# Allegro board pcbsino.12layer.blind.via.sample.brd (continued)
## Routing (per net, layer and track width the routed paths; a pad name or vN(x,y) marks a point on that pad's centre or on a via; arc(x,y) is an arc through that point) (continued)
SODIMM_ETH1_LED2_LINK_ACT_1000/: length 16.2
  TOP w0.114: U19.37 47.29,9.42 R303.2 v2(47.34,9.36)
  INT_L3 w0.091: v2(47.34,9.36) 47.34,6.79 47.99,6.14 50.64,6.14 50.95,5.83 51.97,5.83 52.29,6.16 v3(52.29,6.31)
  SIG_L10 w0.091: v5(52.77,6.34) 52.32,6.34 v3(52.29,6.31)
  BOTTOM w0.114: v5(52.77,6.34) 52.82,6.38 XP1.16
SODIMM_ETH1_MDI0_N: length 15.8
  TOP w0.102: v2(53.41,4.05) 53.33,4.13 53.33,4.59 53.66,4.92 53.66,12.21 53.41,12.46 53,12.46 52.9,12.56 U19.3
  INT_L3 w0.089: v3(56.98,3.36) 56.75,3.58 55.5,3.58 54.74,4.34 53.41,4.34 53.32,4.25 53.32,4.14 v2(53.41,4.05)
  SIG_L10 w0.089: v5(57.69,3.46) 57.67,3.43 57.47,3.43 57.36,3.54 57.17,3.54 v3(56.98,3.36)
  BOTTOM w0.102: XP1.6 57.77,3.38 v5(57.69,3.46)
SODIMM_ETH1_MDI0_P: length 15.7
  TOP w0.102: U19.2 52.99,12.16 53.04,12.21 53.31,12.21 53.41,12.1 53.41,5.03 53.08,4.7 53.08,4.11 v2(53.02,4.05)
  INT_L3 w0.089: v2(53.02,4.05) 53.08,4.11 53.08,4.35 53.31,4.59 54.84,4.59 55.6,3.82 56.84,3.82 v3(56.98,3.96)
  SIG_L10 w0.089: v5(57.7,3.98) 57.5,3.78 57.16,3.78 v3(56.98,3.96)
  BOTTOM w0.102: XP1.8 v5(57.7,3.98)
SODIMM_ETH1_MDI1_N: length 14.1
  TOP w0.102: U19.6 52.99,13.76 53.06,13.68 53.99,13.68 54.6,13.07 54.6,5.16 54.65,5.12 v2(54.65,5.08)
  INT_L3 w0.089: v3(57.2,5.2) 57.02,5.39 54.64,5.39 54.55,5.3 54.55,5.17 v2(54.65,5.08)
  SIG_L10 w0.089: v3(57.2,5.2) 57.38,5.39 57.56,5.39 57.65,5.3 57.65,5.29 v5(57.68,5.26)
SODIMM_ETH1_MDI1_P: length 14.2
  TOP w0.102: v2(54.25,5.07) 54.25,5.07 54.25,5.08 54.35,5.17 54.35,12.97 53.88,13.43 53.06,13.43 52.99,13.36 U19.5
  INT_L3 w0.089: v3(57.2,5.81) 57.02,5.63 54.54,5.63 54.31,5.4 54.31,5.13 v2(54.25,5.07)
  SIG_L10 w0.089: v5(57.68,5.84) 57.6,5.76 57.6,5.72 57.51,5.63 57.38,5.63 v3(57.2,5.81)
SODIMM_ETH1_MDI2_N: length 13.3
  TOP w0.102: U19.8 52.99,14.56 53.06,14.48 54.73,14.48 55.44,13.77 v2(55.44,7.13)
  INT_L3 w0.089: v3(58.13,7) 57.94,7.19 55.5,7.19 v2(55.44,7.13)
  SIG_L10 w0.089: v3(58.13,7) v5(57.64,7)
SODIMM_ETH1_MDI2_P: length 13.1
  TOP w0.102: U19.7 52.99,14.16 53.06,14.23 54.62,14.23 55.19,13.67 55.19,7.48 v2(55.03,7.33)
  INT_L3 w0.089: v3(58.12,7.64) 57.91,7.43 55.14,7.43 v2(55.03,7.33)
  SIG_L10 w0.089: v3(58.12,7.64) 58.06,7.57 v5(57.63,7.57)
SODIMM_ETH1_MDI3_N: length 12.9
  TOP w0.102: v2(56.18,9.03) 56.28,9.13 56.28,14.47 55.06,15.68 53.06,15.68 52.99,15.76 U19.11
  INT_L3 w0.089: v2(56.18,9.03) 56.32,9.17 57.05,9.17 57.28,8.94 58.41,8.94 v3(58.56,8.79)
  SIG_L10 w0.089: v5(58.08,8.8) 58.2,8.8 58.55,8.8 v3(58.56,8.79)
SODIMM_ETH1_MDI3_P: length 12.8
  TOP w0.102: U19.10 52.99,15.36 53.06,15.43 54.96,15.43 56.02,14.36 56.02,9.41 v2(55.82,9.21)
  INT_L3 w0.089: v3(58.56,9.41) 58.56,9.31 58.44,9.18 57.38,9.18 57.15,9.41 56.02,9.41 v2(55.82,9.21)
  SIG_L10 w0.089: v5(58.09,9.41) 58.21,9.41 58.21,9.41 58.56,9.41 v3(58.56,9.41)
SODIMM_GPIO1_16: length 66.6
  TOP w0.114: XP1.151 58.62,49.57 v2(57.55,49.57)
  TOP w0.12: v8(19.87,19.97) U6.D27
  INT_L3 w0.091: v3(44.47,50.86) 45.15,51.54 45.83,51.54 46.09,51.8 56.23,51.8 57.37,50.66 57.37,49.75 v2(57.55,49.57)
  SIG_L5 w0.091: v3(44.47,50.86) 44.47,50.43 41.98,47.94 41.98,44.84 40.86,43.73 31.87,43.73 30.23,42.09 30.23,41.97 30.2,41.94 30.2,30.09 30.23,30.06 30.23,24.97 29.66,24.4 29.36,24.4 28.49,23.53 28.49,23.26 26.5,21.27 25.62,21.27 24.7,20.35 22.8,20.35 22.04,19.6 20.25,19.6 v8(19.87,19.97)
SODIMM_GPIO1_17: length 86
  TOP w0.114: XP1.149 58.58,48.93 56.58,48.93 v7(56.48,48.83)
  TOP w0.12: U6.C28 19.01,19.11 19.01,17.24 19.37,16.88 v2(19.55,16.88)
  INT_L3 w0.091: v2(19.55,16.88) 20.13,16.29 20.13,15.99 v3(20.16,15.96)
  SIG_L5 w0.091: v7(56.48,48.83) 56.48,47.84 55.96,47.31 55.96,38.49 53.82,36.35 53.82,33.6 53.29,33.07 53.29,31.76 51.47,29.95 51.47,23.06 53.66,20.87 53.66,17.7 51.61,15.65 51.61,14.79 46.8,9.98 45.62,9.98 44.21,8.57 44.19,8.55 41.72,6.09 32.74,6.09 32.5,5.85 26.53,5.85 20.16,12.22 v3(20.16,15.96)
SODIMM_GPIO2_2: length 29.2
  TOP w0.114: v2(56.53,36.56) 54.78,38.32 52.95,38.32 52.92,38.34 v2(52.91,38.34)
  TOP w0.12: v8(39.06,27.98) U6.P4
  INT_L3 w0.091: v8(39.06,27.98) 39.06,28.01 39.69,28.64 41.22,28.64 42.26,29.68 42.26,31.92 42.64,32.3 44.22,32.3 44.58,32.66 44.89,32.66 45.39,33.15 45.9,33.15 47.82,35.07 50.71,35.07 52.65,37 52.65,38.08 v2(52.91,38.34) ; v2(57.62,32.78) 57.62,33.34 56.79,34.18 56.79,36.31 v2(56.53,36.56)
SODIMM_GPIO3_29/AVID: length 56.7
  TOP w0.12: v8(40.67,22.37) U6.G2
  INT_L3 w0.091: v3(47.79,48.68) 48.24,49.13 54.92,49.13 56.15,47.89 56.15,36.44 56.43,36.16 56.43,32.65 56.86,32.22 v2(57.7,32.22)
  SIG_L10 w0.091: v3(47.79,48.68) 47.73,48.62 47.73,45.34 47.41,45.02 47.41,43.79 44.22,40.59 44.22,40.35 44.22,35.02 44.36,34.88 44.36,34.7 44.36,24.45 44.06,24.16 43.2,23.3 42.27,23.3 41.97,23.3 41.59,23.3 v8(40.67,22.37)
SODIMM_GPIO4_0/DEC_INTREQ: length 24.1
  TOP w0.114: v7(56.18,25.91) 56.45,26.18 XP1.73
  TOP w0.12: v8(37.47,22.37) U6.G6
  BOTTOM w0.114: v8(37.47,22.37) 37.86,21.98 38.1,21.98 38.1,21.98 38.43,21.98 38.43,21.98 39.71,21.98 39.71,21.98 40.04,21.98 40.04,21.98 40.83,21.98 40.83,21.98 40.98,21.98 41.57,22.57 42.64,22.57 43.25,21.96 44.93,21.96 44.93,21.95 45.17,21.95 45.18,21.96 48.05,21.96 49.34,23.25 51.76,23.25 52.98,24.47 54.58,24.47 56.01,25.91 v7(56.18,25.91)
SODIMM_GPIO5_4: length 49.6
  TOP w0.12: v8(31.87,22.37) U6.G13
  SIG_L10 w0.091: v8(31.87,22.37) 31.93,22.37 32.35,22.8 32.88,22.8 33.06,22.97 33.06,23.37 34.07,24.37 34.07,24.37 34.09,24.39 34.33,24.39 34.59,24.65 34.59,24.88 37.28,27.57 40.45,27.57 42.34,29.46 42.34,33.8 42.15,33.99 42.15,41.56 46.32,45.73 46.32,48.73 46.73,49.14 53.53,49.14 55.21,50.81 v5(55.21,51.3)
  BOTTOM w0.114: v5(55.21,51.3) 56.5,52.58 XP1.162
SODIMM_GPIO6_16/CLKOUT1: length 61.3
  INT_L3 w0.091: v2(57.57,34.02) 57.27,34.32 v3(57.27,34.51)
  SIG_L5 w0.091: v3(57.27,34.51) 57.27,34.11 52.55,29.39 52.55,23.61 54.54,21.63 54.54,15.4 47.76,8.62 45.92,8.62 45.78,8.48 44.97,8.48 41.97,5.47 38.25,5.47 37.78,5 37.44,5 36.97,5.47 v3(36.29,5.47)
  SIG_L10 w0.091: v3(36.29,5.47) 35.89,5.88 32.42,5.88 32.27,6.03 32.17,6.03 25.72,12.48 25.72,14.87 v5(25.59,15)
SODIMM_GPIO6_18: length 60.3
  TOP w0.12: v8(27.87,20.77) U6.E17
  SIG_L5 w0.091: v8(27.87,20.77) 28.29,21.2 28.29,21.81 28.48,22 28.82,22 29.04,22.22 29.04,22.23 29.09,22.28 29.09,22.53 29.31,22.75 29.97,22.75 30.81,23.6 31.37,23.6 31.56,23.79 31.56,24.3 31.46,24.4 31.46,27.54 31.27,27.73 31.27,28.45 31.47,28.65 31.47,29.13 31.27,29.33 31.27,29.64 30.69,30.22 30.69,30.97 31.44,31.72 31.44,33.08 30.69,33.83 30.69,36.2 31.52,37.03 31.52,39.11 31.67,39.26 31.67,40.59 31.61,40.64 31.61,41.87 32.53,42.79 41.27,42.79 42.63,44.15 42.63,46.42 43.04,46.83 43.04,48.2 44.57,49.72 44.82,49.72 46.17,51.07 v3(46.27,51.07)
  SIG_L10 w0.091: v3(46.27,51.07) 47.26,50.08 50.21,50.08 50.39,50.26 53.61,50.26 55.06,51.7 56.23,51.7 57.75,50.18 v5(57.85,50.18)
  BOTTOM w0.114: v5(57.85,50.18) XP1.154
SODIMM_GPIO6_19: length 91
  TOP w0.114: XP1.193 58.62,62.18 56.21,62.18 v7(56.05,62.34) ; v2(22.15,13.56) 21.02,14.69 R173.2
  INT_L3 w0.091: v2(22.15,13.56) 22.15,13.31 22.66,12.8 22.84,12.8 v3(22.93,12.71)
  SIG_L5 w0.091: v3(22.93,12.71) 23.56,12.09 23.56,10.7 26.95,7.31 27.9,7.31 28.16,7.05 40.6,7.05 44.4,10.85 46.44,10.85 50.35,14.76 50.35,16.26 51.87,17.78 51.87,21.62 50.82,22.67 50.82,30.22 52.64,32.04 52.64,33.34 53.16,33.87 53.16,36.62 55.08,38.54 55.08,51.22 55.87,52 55.87,53.33 55.55,53.65 55.55,61.84 v7(56.05,62.34)
SODIMM_HDMI1_CEC: length 62.9
  TOP w0.114: v2(25.37,18.4) 25.52,18.41 U6.B20
  INT_L3 w0.091: v2(25.37,18.4) 25.37,18.35 25.21,18.2 25.21,16.37 24.35,15.51 24.35,14.54 23.78,13.97 23.78,13.93 23.76,13.91 23.76,12.53 21.66,10.43 v3(21.66,9.59)
  SIG_L10 w0.091: v5(58.95,11.77) 59.29,11.43 59.29,2.09 57.85,0.65 46.3,0.65 43.37,3.57 37.31,3.57 37.1,3.36 33.41,3.36 30.99,5.78 26.69,5.78 22.88,9.59 v3(21.66,9.59)
SODIMM_HDMI1_CLOCK_N: length 64.4
  TOP w0.102: U6.AG16 29.07,38.94 28.65,39.37 28.65,40.04 v2(28.31,40.37)
  INT_L3 w0.089: v2(28.31,40.37) 28.46,40.54 28.97,40.54 30.81,42.38 41.67,42.38 44.49,39.56 47.07,39.56 47.63,39 49.48,39 49.75,39.27 50.17,39.27 50.31,39.13 v3(50.31,39.1)
  SIG_L10 w0.089: v3(50.31,39.1) 50.54,39.33 51.03,39.33 53.04,37.33 53.04,37.09 53.26,36.87 53.42,36.87 53.5,36.79 53.5,36.68 53.42,36.6 53.26,36.6 53.04,36.38 53.04,36.07 53.26,35.85 53.42,35.85 53.5,35.77 53.5,35.66 53.42,35.59 53.26,35.59 53.04,35.37 53.04,35.06 53.26,34.84 53.42,34.84 53.5,34.76 53.5,34.65 53.42,34.57 53.26,34.57 53.04,34.35 53.04,28.7 52.89,28.55 52.89,25.82 53.04,25.67 53.04,23.38 54.33,22.09 54.33,14.45 55.34,13.45 55.65,13.45 55.8,13.6 55.91,13.6 55.99,13.52 55.99,13.41 55.84,13.26 55.84,12.95 56.06,12.73 56.37,12.73 56.52,12.88 56.63,12.88 56.71,12.81 56.71,12.7 56.55,12.54 56.55,12.23 57.09,11.7 57.09,11.16 56.92,10.99 56.52,10.99 56.43,11.07 v5(56.43,11.21)
  BOTTOM w0.102: XP1.32 57.36,11.18 57.14,10.96 56.56,10.96 56.43,11.09 v5(56.43,11.21)
SODIMM_HDMI1_CLOCK_P: length 64.5
  TOP w0.102: v2(28.24,40.81) 28.36,40.81 28.72,40.45 28.72,40.33 28.9,40.15 28.9,39.74 U6.AH16
  INT_L3 w0.089: v3(50.31,39.71) 50.11,39.51 49.65,39.51 49.38,39.24 47.73,39.24 47.17,39.8 44.59,39.8 41.77,42.62 30.71,42.62 28.87,40.78 28.26,40.78 v2(28.24,40.81)
  SIG_L10 w0.089: v5(56.46,10.58) 56.48,10.58 56.65,10.74 57.02,10.74 57.33,11.06 57.33,11.8 56.8,12.33 56.8,12.44 56.95,12.6 56.95,12.91 56.73,13.13 56.42,13.13 56.27,12.97 56.16,12.97 56.08,13.05 56.08,13.16 56.23,13.31 56.23,13.62 56.01,13.84 55.7,13.84 55.55,13.69 55.44,13.69 54.58,14.55 54.58,22.19 53.28,23.48 53.28,25.77 53.13,25.92 53.13,28.45 53.28,28.6 53.28,34.25 53.36,34.33 53.52,34.33 53.74,34.55 53.74,34.86 53.52,35.08 53.36,35.08 53.28,35.16 53.28,35.27 53.36,35.34 53.52,35.34 53.74,35.56 53.74,35.87 53.52,36.09 53.36,36.09 53.28,36.17 53.28,36.28 53.36,36.36 53.52,36.36 53.74,36.58 53.74,36.89 53.52,37.11 53.36,37.11 53.28,37.19 53.28,37.43 51.13,39.57 50.45,39.57 v3(50.31,39.71)
  BOTTOM w0.102: XP1.30 v5(56.46,10.58)
SODIMM_HDMI1_DATA0_N: length 64.1
  TOP w0.102: v2(27.37,42.91) 27.42,42.86 27.42,40.4 27.85,39.97 27.85,39.37 28.27,38.94 U6.AG17
  INT_L3 w0.089: v3(49.11,39.92) 48.92,40.1 48.92,40.33 48.61,40.64 44.8,40.64 42.1,43.33 27.79,43.33 27.48,43.02 v2(27.37,42.91)
  SIG_L10 w0.089: v5(55.02,12.9) 54.89,12.78 53.74,12.78 53.48,13.03 53.48,13.49 53.71,13.72 53.71,14.09 53.48,14.32 53.48,14.5 53.71,14.73 53.71,15.11 53.48,15.34 53.48,15.52 53.71,15.75 53.71,16.13 53.48,16.35 53.48,16.53 53.71,16.76 53.71,17.14 53.48,17.37 53.48,17.81 53.87,18.19 53.87,21.68 52.54,23 52.54,37.01 51.01,38.54 49.66,38.54 48.92,39.28 48.92,39.73 v3(49.11,39.92)
  BOTTOM w0.102: XP1.38 57.26,12.98 57.07,12.79 55.14,12.79 v5(55.02,12.9)
SODIMM_HDMI1_DATA0_P: length 64.1
  TOP w0.102: v2(27.8,42.91) 27.78,42.91 27.68,42.81 27.68,42.42 27.8,42.29 27.8,42.12 27.68,41.99 27.68,41.81 27.8,41.68 27.8,41.51 27.68,41.38 27.68,41.2 27.8,41.07 27.8,40.9 27.68,40.77 27.68,40.5 28.1,40.08 28.1,39.74 U6.AH17
  INT_L3 w0.089: v3(48.5,39.92) 48.68,40.1 48.68,40.23 48.51,40.4 44.7,40.4 42,43.09 34.44,43.09 34.34,42.99 34.17,42.99 34.07,43.09 33.91,43.09 33.8,42.99 33.64,42.99 33.54,43.09 33.37,43.09 33.27,42.99 33.11,42.99 33,43.09 32.84,43.09 32.74,42.99 32.57,42.99 32.47,43.09 32.31,43.09 32.2,42.99 32.04,42.99 31.94,43.09 31.77,43.09 31.67,42.99 31.51,42.99 31.4,43.09 31.24,43.09 31.14,42.99 30.97,42.99 30.87,43.09 30.71,43.09 30.6,42.99 30.44,42.99 30.34,43.09 30.17,43.09 30.07,42.99 29.91,42.99 29.8,43.09 29.64,43.09 29.54,42.99 29.37,42.99 29.27,43.09 29.1,43.09 29,42.99 28.84,42.99 28.74,43.09 28.57,43.09 28.47,42.99 28.3,42.99 28.2,43.09 27.89,43.09 27.8,43 v2(27.8,42.91)
  SIG_L10 w0.089: v3(48.5,39.92) 48.68,39.73 48.68,39.18 49.56,38.3 50.91,38.3 52.3,36.91 52.3,22.9 53.62,21.58 53.62,18.29 53.24,17.91 53.24,17.27 53.47,17.04 53.47,16.86 53.24,16.63 53.24,16.26 53.47,16.03 53.47,15.85 53.24,15.62 53.24,15.24 53.47,15.01 53.47,14.83 53.24,14.6 53.24,14.22 53.47,13.99 53.47,13.81 53.24,13.59 53.24,12.93 53.64,12.54 54.91,12.54 v5(55.03,12.41)
  BOTTOM w0.102: XP1.36 57.25,12.38 57.09,12.54 55.16,12.54 v5(55.03,12.41)
SODIMM_HDMI1_DATA1_N: length 64.9
  TOP w0.102: U6.AG18 27.09,39.15 27.09,39.81 26.74,40.17 26.74,43.27 v2(26.64,43.37)
  INT_L3 w0.089: v2(26.64,43.37) 26.67,43.41 26.67,43.86 26.9,44.09 42.3,44.09 45.09,41.3 48.92,41.3 49.31,40.92 50.02,40.92 v3(50.16,41.06)
  SIG_L10 w0.089: v5(57.17,14.77) 57,14.6 55.69,14.6 55.29,15 55.29,22.67 54.63,23.33 54.63,26.8 56.01,28.18 56.01,30.49 55.62,30.87 55.62,33.13 56.15,33.67 56.15,37.02 52.87,40.3 51.62,40.3 50.99,40.92 50.32,40.92 50.18,41.06 v3(50.16,41.06)
  BOTTOM w0.102: XP1.44 57.18,14.78 v5(57.17,14.77)
SODIMM_HDMI1_DATA1_P: length 65
  TOP w0.102: U6.AH18 27.47,39.8 26.99,40.27 26.99,40.93 27.09,41.03 27.09,41.23 26.99,41.33 26.99,41.54 27.09,41.64 27.09,41.84 26.99,41.94 26.99,42.15 27.09,42.25 27.09,42.45 26.99,42.55 26.99,43.4 v2(27.02,43.42)
  INT_L3 w0.089: v2(27.02,43.42) 26.92,43.52 26.92,43.76 27,43.85 27.45,43.85 27.58,43.73 27.72,43.73 27.85,43.85 27.99,43.85 28.11,43.73 28.25,43.73 28.38,43.85 28.52,43.85 28.65,43.73 28.79,43.73 28.91,43.85 29.05,43.85 29.18,43.73 29.32,43.73 29.45,43.85 29.59,43.85 29.71,43.73 29.85,43.73 29.98,43.85 30.12,43.85 30.25,43.73 30.39,43.73 30.51,43.85 30.65,43.85 30.78,43.73 30.92,43.73 31.05,43.85 31.19,43.85 31.31,43.73 31.45,43.73 31.58,43.85 31.72,43.85 31.85,43.73 31.99,43.73 32.11,43.85 32.25,43.85 32.38,43.73 32.52,43.73 32.65,43.85 42.2,43.85 44.99,41.06 48.82,41.06 49.21,40.68 49.93,40.68 v3(50.16,40.45)
  SIG_L10 w0.089: v3(50.16,40.45) 50.39,40.68 50.89,40.68 51.52,40.06 52.77,40.06 55.91,36.92 55.91,33.77 55.38,33.23 55.38,30.77 55.76,30.39 55.76,28.28 54.39,26.9 54.39,23.23 55.05,22.57 55.05,14.9 55.59,14.36 57,14.36 v5(57.17,14.19)
  BOTTOM w0.102: XP1.42 57.17,14.18 v5(57.17,14.19)
SODIMM_HDMI1_DATA2_N: length 65.4
  TOP w0.102: v2(25.68,43.93) 25.72,43.89 25.72,40.35 26.25,39.82 26.25,39.37 26.67,38.94 U6.AG19
  INT_L3 w0.089: v3(51.81,41.75) 51.67,41.61 51.16,41.61 50.82,41.95 45.51,41.95 42.63,44.83 26.09,44.83 25.76,44.5 25.76,44.01 v2(25.68,43.93)
  SIG_L10 w0.089: v3(51.81,41.75) 51.91,41.64 52.61,41.64 56.72,37.53 56.72,33.42 56.29,32.98 56.29,31.35 56.72,30.92 56.72,27.85 55.36,26.49 55.36,23.67 55.95,23.09 55.95,16.48 56.04,16.39 56.96,16.39 v5(57.14,16.57)
  BOTTOM w0.102: v5(57.14,16.57) 57.15,16.58 XP1.50
SODIMM_HDMI1_DATA2_P: length 65.3
  TOP w0.102: v2(26.06,43.96) 25.98,43.87 25.98,43.19 26.13,43.04 26.13,42.89 25.98,42.74 25.98,42.58 26.13,42.43 26.13,42.28 25.98,42.13 25.98,41.97 26.13,41.82 26.13,41.67 25.98,41.52 25.98,41.36 26.13,41.21 26.13,41.06 25.98,40.91 25.98,40.45 26.51,39.92 26.51,39.73 U6.AH19
  INT_L3 w0.089: v2(26.06,43.96) 26,44.02 26,44.4 26.19,44.59 26.38,44.59 26.48,44.49 26.64,44.49 26.74,44.59 26.91,44.59 27.01,44.49 27.18,44.49 27.28,44.59 27.44,44.59 27.54,44.49 27.71,44.49 27.81,44.59 27.98,44.59 28.08,44.49 28.24,44.49 28.34,44.59 28.51,44.59 28.61,44.49 28.78,44.49 28.88,44.59 29.04,44.59 29.14,44.49 29.31,44.49 29.41,44.59 29.58,44.59 29.68,44.49 29.84,44.49 29.94,44.59 42.53,44.59 45.41,41.71 50.72,41.71 51.06,41.36 51.58,41.36 v3(51.81,41.14)
  SIG_L10 w0.089: v3(51.81,41.14) 51.81,41.16 52.05,41.4 52.51,41.4 56.48,37.43 56.48,33.52 56.05,33.08 56.05,31.26 56.48,30.82 56.48,27.95 55.12,26.59 55.12,23.57 55.71,22.99 55.71,16.38 55.94,16.15 57.01,16.15 v5(57.17,15.99)
  BOTTOM w0.102: XP1.48 57.18,15.98 v5(57.17,15.99)
SODIMM_HDMI1_DDC_SCL: length 53.7
  TOP w0.114: v2(52.22,3.31) 52.22,3.31 52.3,3.23 52.46,3.23 52.6,3.37 53.99,3.37 56.61,5.98 56.61,9.08 56.91,9.38 XP1.25
  TOP w0.12: v8(21.47,19.17) U6.C25
  INT_L3 w0.091: v2(52.22,3.31) 52.21,3.31 52.21,3.37 v3(51.96,3.62)
  SIG_L10 w0.091: v8(21.47,19.17) 21.84,18.81 21.84,15.28 21.63,15.07 21.63,13.66 22.42,12.87 22.42,12.61 23.46,11.57 25.98,11.57 32.02,5.53 32.15,5.53 33.06,4.61 33.97,4.61 34.13,4.77 36.09,4.77 36.16,4.7 42.72,4.7 43.55,3.87 46.14,3.87 47.61,5.35 50.54,5.35 51.96,3.93 v3(51.96,3.62)
SODIMM_HDMI1_DDC_SDA: length 59.1
  TOP w0.114: XP1.31 58.8,11.18 v2(58.84,11.14)
  TOP w0.12: U6.F17 27.87,21.58 v8(27.86,21.58)
  INT_L3 w0.091: v2(58.84,11.14) 58.79,11.09 58.79,10.68 v3(58.78,10.66)
  SIG_L10 w0.091: v3(58.78,10.66) 59.07,10.36 59.07,2.18 57.8,0.91 56.07,0.91 55.47,1.51 55.47,2.5 54.25,3.72 53.03,3.72 51.05,5.7 47.52,5.7 46.65,4.84 45.05,4.84 43.81,6.08 43.35,6.08 43.26,6.18 36.45,6.18 36.16,6.46 32.35,6.46 26.93,11.88 26.93,14.82 27.12,15.01 27.12,18.48 26.67,18.93 26.67,20.79 27.29,21.42 27.7,21.42 v8(27.86,21.58)
SODIMM_HDMI1_HPD: length 65.8
  TOP w0.114: U6.B21 v2(24.66,18.4)
  INT_L3 w0.091: v3(21.54,8.94) 21.25,9.23 21.25,10.4 23.51,12.66 23.51,14.01 24.02,14.52 24.02,15.56 24.86,16.4 24.86,17.95 24.66,18.15 v2(24.66,18.4)
  SIG_L10 w0.091: v3(21.54,8.94) 23.22,8.94 26.64,5.52 30.84,5.52 33.23,3.14 37.19,3.14 37.4,3.35 43.11,3.35 46.03,0.43 57.69,0.43 57.71,0.43 57.94,0.43 58,0.49 58.02,0.49 58.06,0.55 59.51,2 59.51,2.18 59.51,13.17 v5(59.12,13.55)
SODIMM_I2C5_SCL/UART6_TXD: length 63.4
  INT_L3 w0.091: v2(57.85,42.99) 57.73,42.86 57.73,41.11 v3(57.6,40.98)
  SIG_L5 w0.091: v3(45.61,8.88) 47.71,8.88 54.32,15.49 54.32,21.54 52.34,23.52 52.34,29.48 56.38,33.53 56.38,35.8 57.6,37.02 v3(57.6,40.98)
  SIG_L10 w0.091: v3(45.61,8.88) 45.43,9.06 44.65,9.06 44.34,8.74 39.05,8.74 36.29,11.5 35.33,11.5 34.08,12.75 33.61,12.75 32.24,14.12 32.24,16.67 31.94,16.97 31.94,18.73 32.48,19.27 v5(32.55,19.27)
SODIMM_I2C5_SDA/UART6_RXD: length 64.8
  INT_L3 w0.091: v3(56.74,41.36) 57.34,41.97 57.34,43.98 58.11,44.74 v2(58.11,44.79)
  SIG_L5 w0.091: v3(46.07,9.36) 47.88,9.36 54.1,15.58 54.1,21.06 52.12,23.04 52.12,29.66 54.96,32.5 54.96,36.78 56.74,38.55 v3(56.74,41.36)
  SIG_L10 w0.091: v3(46.07,9.36) 44.64,9.36 44.25,8.96 39.14,8.96 36.63,11.47 36.38,11.72 35.42,11.72 34.17,12.97 34.03,12.97 32.46,14.54 32.46,16.76 32.22,17 32.22,17.92 v5(32.26,17.96)
  BOTTOM w0.114: v5(32.26,17.96) 32.54,18.23 R243.2
SODIMM_LDOUSB_IN: length 24.4
  TOP w0.114: R50.1 41.27,52.57 42.1,52.57 TP16.1 42.89,53.35 v2(42.89,54.01)
  INT_L3 w0.091: v2(42.89,54.01) 43.93,55.05 46.3,55.05 47.72,56.48 47.72,58.53 48.51,59.32 48.51,60.24 50.74,62.47 52.35,62.47 52.44,62.56 v3(52.44,62.57)
  SIG_L10 w0.091: v3(52.44,62.57) 52.47,62.57 52.67,62.78 v5(57.14,62.78)
  BOTTOM w0.114: XP1.196 v5(57.14,62.78)
SODIMM_MCASP2_ACLKX: length 62.1
  TOP w0.114: XP1.137 56.43,45.38 v2(55.67,46.14) ; v2(26.61,17.62) 26.67,17.67 U6.A19
  INT_L3 w0.091: v2(26.61,17.62) 26.59,17.59 26.59,17.13 v3(26.66,17.06) ; v2(55.67,46.14) 54.93,46.88 53.5,46.88 52.3,48.07 49.97,48.07 49.22,48.83 48.63,48.83 47.95,48.15 44.52,48.15 43.98,47.61 v3(43.83,47.61)
  SIG_L5 w0.091: v3(43.83,47.61) 43.76,47.54 43.76,47.23 42.85,46.33 42.85,43.91 41.37,42.43 32.71,42.43 31.83,41.56 31.83,40.73 31.96,40.6 31.96,37.24 32.29,36.9 32.29,31.83 32.01,31.55 31.71,31.55 31.49,31.33 31.49,30.53 31.49,30.53 31.49,29.42 32.02,28.89 32.02,28.66 31.49,28.13 31.49,27.82 32.07,27.24 32.07,25.15 32.29,24.93 32.29,23.64 31.28,22.63 31.28,21.99 27.13,17.83 26.69,17.39 26.69,17.08 v3(26.66,17.06)
SODIMM_MCASP2_AXR0: length 62.8
  TOP w0.114: v2(29.53,19.09) 29.85,18.77 U6.B15 ; XP1.139 57.25,45.98 57.22,46.01 56.25,46.01 v2(55.67,46.6)
  INT_L3 w0.091: v3(29.51,18.28) 29.53,18.3 v2(29.53,19.09) ; v2(55.67,46.6) 55.14,47.13 53.81,47.13 v3(52.98,47.97)
  SIG_L5 w0.091: v3(29.51,18.28) 29.28,18.05 29.28,16.81 32.35,13.74 43.17,13.74 47.34,17.92 47.34,19.77 48.13,20.55 48.13,32.11 51.19,35.17 51.19,46.18 v3(52.98,47.97)
SODIMM_MCASP2_AXR1: length 61.4
  TOP w0.114: v2(29.48,17.59) 29.49,17.59 U6.A15 ; v2(55.62,47.51) 56.15,47.51 56.48,47.18 XP1.143
  INT_L3 w0.091: v2(55.62,47.51) 54.17,47.51 53.2,48.48 v3(51.99,48.48) ; v3(29.68,17.1) 29.48,17.31 v2(29.48,17.59)
  SIG_L5 w0.091: v3(51.99,48.48) 50.97,47.46 50.97,35.26 47.91,32.2 47.91,20.64 47.12,19.86 47.12,18.01 43.08,13.96 32.44,13.96 29.68,16.72 v3(29.68,17.1)
SODIMM_MCASP2_FSX: length 62
  TOP w0.114: XP1.145 56.57,47.78 56.2,48.15 v2(55.19,48.15) ; 27.47,17.43 27.47,17.39 v2(27.47,17.39)
  TOP w0.12: U6.A18 27.47,17.43
  INT_L3 w0.091: v2(55.19,48.15) 55.01,48.32 v3(54.07,48.32) ; v2(27.47,17.39) 27.75,17.11 v3(27.93,17.11)
  SIG_L5 w0.091: v3(54.07,48.32) 54.07,45.78 51.41,43.12 51.41,35.07 49.79,33.45 49.79,31.02 49.04,30.26 49.04,24.65 48.45,24.06 48.45,20.57 47.56,19.68 47.56,17.83 43.26,13.53 31.51,13.53 v3(27.93,17.11)
SODIMM_MICROSD_MMC1_CLK: length 34.4
  TOP w0.12: v8(37.47,32.77) U6.W6
  SIG_L5 w0.091: v3(41.9,26.38) 41.67,26.15 41.09,26.15 41.01,26.23 41.01,26.42 40.93,26.51 40.81,26.51 40.73,26.42 40.73,26.23 40.65,26.15 40.43,26.15 40.1,26.48 40.1,28.61 40,28.72 38.12,28.72 37.47,29.36 v8(37.47,32.77)
  SIG_L10 w0.091: v3(41.9,26.38) 41.27,26.38 40.86,25.97 40.86,24.63 41.27,24.22 42.89,24.22 v5(42.97,24.14)
  BOTTOM w0.114: XP1.80 56.79,27.98 54.22,25.41 52.57,25.41 51.21,24.05 48.54,24.05 47.85,23.36 43.73,23.36 42.97,24.12 v5(42.97,24.14)
SODIMM_MICROSD_MMC1_CMD: length 34.4
  TOP w0.12: v8(37.47,33.57) U6.Y6
  SIG_L5 w0.091: v8(37.47,33.57) 37.1,33.21 37.1,32.94 37.09,32.93 37.09,32.62 37.1,32.61 37.1,32.32 37.02,32.24 36.98,32.24 36.9,32.16 36.9,32.05 36.98,31.97 37.02,31.97 37.1,31.89 37.1,31.77 37.02,31.69 36.98,31.69 36.9,31.61 36.9,31.5 36.98,31.42 37.02,31.42 37.1,31.34 37.1,31.22 37.02,31.14 36.98,31.14 36.9,31.06 36.9,30.95 36.98,30.87 37.02,30.87 37.1,30.79 37.1,30.67 37.02,30.59 36.98,30.59 36.9,30.51 36.9,30.4 36.98,30.32 37.02,30.32 37.1,30.24 37.1,30.13 37.02,30.05 36.98,30.05 36.9,29.97 36.9,29.85 36.98,29.77 37.02,29.77 37.1,29.69 37.1,29.25 37.94,28.41 39.55,28.41 39.72,28.24 39.72,26.33 40.25,25.79 v3(41.93,25.79)
  SIG_L10 w0.091: v3(41.93,25.79) 41.72,25.79 41.42,25.49 41.42,25.09 41.96,24.55 v5(42.97,24.55)
  BOTTOM w0.114: XP1.82 57.04,28.58 54.18,25.72 52.23,25.72 50.86,24.35 48.25,24.35 47.62,23.71 43.88,23.71 43.04,24.55 v5(42.97,24.55)
SODIMM_MICROSD_MMC1_DAT0: length 34.3
  TOP w0.12: v8(37.47,34.37) U6.AA6
  SIG_L5 w0.091: v8(37.47,34.37) 37.74,34.37 37.89,34.23 37.89,32.34 37.76,32.21 37.76,32.06 37.89,31.94 37.89,31.79 37.76,31.66 37.76,31.52 37.89,31.39 37.89,31.24 37.76,31.11 37.76,30.97 37.89,30.84 37.89,30.69 37.76,30.57 37.76,30.42 37.89,30.29 37.89,30.14 37.76,30.02 37.76,29.87 37.89,29.74 37.89,29.35 38.22,29.02 40.33,29.02 40.58,28.77 40.58,28.55 40.66,28.47 40.78,28.47 40.86,28.39 40.86,28.28 40.78,28.2 40.66,28.2 40.58,28.12 40.58,28 40.66,27.92 40.78,27.92 40.86,27.84 40.86,27.73 40.78,27.65 40.66,27.65 40.58,27.57 40.58,27.19 40.86,26.91 42.13,26.91 v3(42.16,26.94)
  SIG_L10 w0.091: v5(43.37,24.8) 43.63,25.06 43.63,26.25 42.94,26.94 v3(42.16,26.94)
  BOTTOM w0.114: XP1.84 57.3,29.18 54.12,26 52.17,26 52.03,25.86 50.77,24.6 48,24.6 47.54,24.14 44.42,24.14 43.76,24.8 v5(43.37,24.8)
SODIMM_MICROSD_MMC1_DAT1: length 34.7
  TOP w0.12: v8(39.07,33.57) U6.Y4
  SIG_L5 w0.091: v3(43.19,25.63) 43.26,25.63 43.27,25.64 43.3,25.64 43.6,25.95 43.6,27.3 43.68,27.38 43.75,27.38 43.83,27.46 43.83,27.58 43.75,27.66 43.68,27.66 43.6,27.74 43.6,27.85 43.68,27.93 43.75,27.93 43.83,28.01 43.83,28.13 43.75,28.21 43.68,28.21 43.6,28.29 43.6,28.4 43.68,28.48 43.75,28.48 43.83,28.56 43.83,28.67 43.75,28.76 43.68,28.76 43.6,28.84 43.6,28.95 43.68,29.03 43.75,29.03 43.83,29.11 43.83,29.22 43.75,29.3 43.68,29.3 43.6,29.38 43.6,29.5 43.68,29.58 43.75,29.58 43.83,29.66 43.83,29.77 43.75,29.85 43.68,29.85 43.6,29.93 43.6,30.05 43.68,30.13 43.75,30.13 43.83,30.21 43.83,30.32 43.75,30.4 43.68,30.4 43.6,30.48 43.6,30.59 43.68,30.68 43.75,30.68 43.83,30.76 43.83,30.87 43.75,30.95 43.68,30.95 43.6,31.03 43.6,31.14 43.68,31.22 43.75,31.22 43.83,31.3 43.83,31.42 43.75,31.5 43.68,31.5 43.6,31.58 43.6,31.69 43.68,31.77 43.75,31.77 43.83,31.85 43.83,31.97 43.75,32.05 43.68,32.05 43.6,32.13 43.6,32.75 42.36,34 41.01,34 40.21,33.2 39.49,33.2 39.11,33.57 v8(39.07,33.57)
  SIG_L10 w0.091: v5(43.07,25.16) 43.07,25.41 43.17,25.51 43.17,25.6 v3(43.19,25.63)
  BOTTOM w0.114: v5(43.07,25.16) 43.88,25.16 44.47,24.57 47.34,24.57 47.62,24.85 50.68,24.85 51.78,25.96 52.07,26.24 54.02,26.24 56.91,29.13 56.91,29.67 57.03,29.78 XP1.86
SODIMM_MICROSD_MMC1_DAT2: length 34.7
  TOP w0.12: v8(38.26,34.37) U6.AA5
  SIG_L5 w0.091: v8(38.26,34.37) 38.26,33.64 38.72,33.19 39.19,33.19 39.39,32.98 40.45,32.98 41.19,33.72 42.13,33.72 43.25,32.6 43.25,32.2 43.12,32.07 43.12,31.93 43.25,31.8 43.25,31.65 43.12,31.53 43.12,31.38 43.25,31.25 43.25,31.1 43.12,30.98 43.12,30.83 43.25,30.7 43.25,30.55 43.12,30.43 43.12,30.28 43.25,30.15 43.25,30.01 43.12,29.88 43.12,29.73 43.25,29.61 43.25,29.46 43.12,29.33 43.12,29.18 43.25,29.06 43.25,28.91 43.12,28.78 43.12,28.63 43.25,28.51 43.25,28.36 43.12,28.23 43.12,28.09 43.25,27.96 43.25,27.81 43.12,27.68 43.12,27.54 43.25,27.41 43.25,27.11 v3(42.59,26.45)
  SIG_L10 w0.091: v3(42.59,26.45) 42.51,26.38 42.51,26.1 v5(42.46,26.05)
  BOTTOM w0.114: XP1.88 56.7,30.38 56.58,30.27 56.58,29.15 53.92,26.48 51.97,26.48 51.54,26.06 50.59,25.11 47.34,25.11 47.11,24.88 44.82,24.88 44.06,25.64 42.89,25.64 42.49,26.05 v5(42.46,26.05)
SODIMM_MICROSD_MMC1_DAT3: length 34.9
  TOP w0.12: v8(39.87,33.57) U6.Y3
  SIG_L5 w0.091: v8(39.87,33.57) 40.55,34.25 42.54,34.25 44.19,32.61 44.19,25.9 43.3,25.01 42.7,25.01 42.59,25.12 v3(42.59,25.16)
  SIG_L10 w0.091: v5(43.22,26.15) 43.17,26.1 43.1,26.1 42.59,25.59 v3(42.59,25.16)
  BOTTOM w0.114: XP1.90 56.79,30.98 56.33,30.52 56.33,29.23 53.82,26.72 51.87,26.72 51.3,26.16 50.53,25.39 47.24,25.39 46.98,25.13 45.25,25.13 44.45,25.93 43.39,25.93 43.22,26.1 v5(43.22,26.15)
SODIMM_MICROSD_MMC1_SDCD: length 49.9
  TOP w0.12: v8(36.67,32.77) U6.W7
  INT_L3 w0.091: v3(58.18,20.16) 58.13,20.21 v2(57.73,20.21)
  SIG_L8 w0.091: v8(36.67,32.77) 36.67,31.66 36.83,31.5 36.83,30.8 37.26,30.38 37.26,29.75 38.19,28.82 38.82,28.82 40.39,27.25 40.39,24.4 42.06,22.72 43.17,22.72 43.88,22.01 43.88,13.44 47.98,9.34 55.33,9.34 58.57,12.58 58.57,19.77 v3(58.18,20.16)
SODIMM_MICROSD_MMC1_SDWP: length 54.7
  TOP w0.114: U6.Y9 34.62,33.17 v8(34.23,33.57)
  INT_L3 w0.091: v2(58.06,21.98) 58.08,22.01 58.36,22.01 v3(58.49,21.88)
  SIG_L8 w0.091: v8(34.23,33.57) 34.71,33.08 34.71,32.14 35.48,31.38 35.48,30.92 36.56,29.84 36.56,29.52 37.89,28.19 37.89,22.21 39.01,21.1 39.01,20.2 41.22,17.99 41.63,17.99 43.04,16.57 43.04,13.35 47.74,8.65 55.57,8.65 59.22,12.31 59.22,21.15 v3(58.49,21.88)
SODIMM_PCIE_REF_LJCB_CLK_N: length 34.3
  TOP w0.102: C175.1 29.33,43.54 29.33,44.01 29.89,44.56 43.5,44.56 43.83,44.89 v2(43.83,45.35) ; XP1.121 57.31,40.58 57.13,40.41 56.5,40.41 55.11,41.8 55.11,42.91 54.04,43.98 52.72,43.98 v2(52.6,44.11)
  INT_L3 w0.089: v2(43.83,45.35) 43.83,45.13 44.34,44.63 47.02,44.63 47.71,43.94 52.43,43.94 v2(52.6,44.11)
SODIMM_PCIE_REF_LJCB_CLK_P: length 33.9
  TOP w0.102: XP1.119 57.31,39.98 57.13,40.15 56.39,40.15 54.86,41.69 54.86,42.81 53.94,43.73 52.67,43.73 v2(52.54,43.6) ; C176.1 29.07,43.19 29.07,44.11 29.78,44.82 43.4,44.82 43.5,44.92 v2(43.5,45.02)
  INT_L3 w0.089: v2(43.5,45.02) 43.6,45.02 44.24,44.39 46.92,44.39 47.61,43.7 52.44,43.7 v2(52.54,43.6)
SODIMM_PCIE_RX0_N: length 36.5
  TOP w0.102: v2(42.61,40.53) 42.71,40.42 46.47,40.42 50.72,44.67 50.72,45.53 51.6,46.42 52.56,46.42 52.89,46.09 53.11,46.09 53.44,46.42 54.25,46.42 56.49,44.18 XP1.133 ; U6.AG13 31.44,38.77 v2(31.08,39.13)
  INT_L3 w0.089: v2(31.08,39.13) 30.99,39.22 30.59,39.22 30.2,39.6 30.2,40.72 31.45,41.96 40.7,41.96 42.1,40.55 42.59,40.55 v2(42.61,40.53)
SODIMM_PCIE_RX0_P: length 36.5
  TOP w0.102: XP1.131 57.31,43.58 57.13,43.75 57.13,43.82 57.03,43.93 56.38,43.93 54.14,46.16 53.55,46.16 53.22,45.83 52.78,45.83 52.45,46.16 51.71,46.16 50.97,45.42 50.97,44.56 46.58,40.17 42.71,40.17 42.61,40.07 v2(42.61,39.99) ; U6.AH13 31.16,39.88 v2(31.16,39.94)
  INT_L3 w0.089: v2(42.61,39.99) 42.61,40.06 42.36,40.31 42,40.31 40.6,41.72 31.55,41.72 30.45,40.62 30.45,39.7 30.69,39.46 30.98,39.46 31.12,39.6 31.12,39.9 v2(31.16,39.94)
SODIMM_PCIE_RX1_N: length 36.5
  TOP w0.102: v2(40.23,40.42) 40.33,40.53 41.17,40.53 41.67,41.03 46.4,41.03 49.88,44.51 49.88,47.05 50.54,47.71 50.89,47.71 51.26,48.08 51.26,48.43 51.47,48.65 51.83,48.65 52.19,49.01 52.19,49.37 52.41,49.58 52.76,49.58 53.12,49.95 53.12,50.3 53.34,50.52 53.69,50.52 54.06,50.88 54.06,51.24 54.27,51.45 54.63,51.45 54.99,51.81 54.99,52.17 56.35,53.53 56.35,54.5 56.53,54.67 57.04,54.67 57.33,54.38 XP1.167 ; U6.AG11 33.4,39.1 v2(33.52,39.1)
  INT_L3 w0.089: v2(33.52,39.1) 33.84,39.42 34.18,39.42 34.5,39.74 34.5,40.77 34.78,41.05 37.93,41.05 38.46,40.51 40.14,40.51 v2(40.23,40.42)
SODIMM_PCIE_RX1_P: length 36.4
  TOP w0.102: XP1.169 57.31,54.98 57.25,54.93 57.16,54.93 57.16,54.92 57.15,54.92 57.15,54.93 56.43,54.93 56.1,54.6 56.1,53.64 54.74,52.27 54.74,51.92 54.52,51.7 54.17,51.7 53.8,51.34 53.8,50.98 53.59,50.77 53.23,50.77 52.87,50.41 52.87,50.05 52.66,49.84 52.3,49.84 51.94,49.47 51.94,49.12 51.72,48.9 51.37,48.9 51,48.54 51,48.18 50.79,47.97 50.43,47.97 49.62,47.16 49.62,44.62 46.3,41.29 41.57,41.29 41.06,40.78 40.38,40.78 v2(40.25,40.91) ; U6.AH11 33.41,39.92 v2(33.52,39.92)
  INT_L3 w0.089: v2(33.52,39.92) 33.77,39.66 34.08,39.66 34.26,39.84 34.26,40.87 34.68,41.29 38.03,41.29 38.56,40.75 40.1,40.75 v2(40.25,40.91)
SODIMM_PCIE_TX0_N: length 32.8
  TOP w0.102: v2(54.51,45.01) 54.51,44.86 56.13,43.24 56.13,42.59 56.51,42.21 57.13,42.21 57.31,42.38 XP1.127 ; C169.2 30.85,43.29 30.85,43.86 31.13,44.13 43.78,44.13 45.13,45.48 v2(45.13,45.58)
  INT_L3 w0.089: v2(54.51,45.01) 54.35,45.01 52.61,46.75 51.31,46.75 51,47.05 50.61,47.05 50.3,46.75 50.11,46.75 49.81,47.05 49.42,47.05 49.11,46.75 46.41,46.75 45.27,45.61 45.26,45.61 45.23,45.58 v2(45.13,45.58)
SODIMM_PCIE_TX0_P: length 33.2
  TOP w0.102: v2(54.04,44.69) 54.32,44.69 55.87,43.14 55.87,42.48 56.4,41.95 57.13,41.95 57.31,41.78 XP1.125 ; C168.2 31.34,43.07 31.11,43.29 31.11,43.75 31.23,43.88 31.5,43.88 31.59,43.79 31.59,43.76 31.68,43.68 31.81,43.68 31.9,43.76 31.9,43.79 31.99,43.88 32.11,43.88 32.2,43.79 32.2,43.76 32.29,43.68 32.42,43.68 32.51,43.76 32.51,43.79 32.6,43.88 43.88,43.88 45.33,45.33 45.53,45.33 v2(45.56,45.3)
  INT_L3 w0.089: v2(45.56,45.3) 45.56,45.33 45.53,45.35 45.53,45.53 46.51,46.51 49.21,46.51 49.52,46.81 49.71,46.81 50.01,46.51 50.4,46.51 50.71,46.81 50.9,46.81 51.21,46.51 52.51,46.51 54.12,44.89 54.12,44.77 v2(54.04,44.69)
SODIMM_PCIE_TX1_N: length 33.5
  TOP w0.102: XP1.173 57.31,56.18 57.14,56.35 56.41,56.35 55.62,55.56 55.62,54.19 48.36,46.94 48.36,46.56 48.01,46.2 47.63,46.2 47.43,46 47.43,45.62 47.08,45.27 46.7,45.27 46.49,45.07 46.49,44.69 46.14,44.34 45.76,44.34 44.62,43.19 32.94,43.19 32.83,43.09 32.83,42.68 C174.2
SODIMM_PCIE_TX1_P: length 34.1
  TOP w0.102: XP1.175 57.31,56.78 57.13,56.6 56.3,56.6 55.36,55.67 55.36,54.3 48.11,47.04 48.11,46.66 47.91,46.46 47.53,46.46 47.18,46.11 47.18,45.73 46.97,45.52 46.59,45.52 46.24,45.17 46.24,44.79 46.04,44.59 45.66,44.59 44.51,43.45 32.83,43.45 32.58,43.2 32.58,42.61 32.47,42.5 C172.2
SODIMM_PWRON: length 30
  TOP w0.114: R27.2 C22.1 v2(52.59,53.54) ; XP1.165 57.31,53.78 57.12,53.58 v2(56.86,53.58)
  INT_L3 w0.091: v2(30.73,54.62) 30.73,54.6 31.49,53.83 32.92,53.83 33,53.75 34.88,53.75 34.95,53.83 35.29,53.83 35.48,53.63 41.29,53.63 41.6,53.33 43.66,53.33 44.32,53.99 51.91,53.99 52.36,53.54 v2(52.59,53.54) 56.82,53.54 v2(56.86,53.58)
SODIMM_SATA1_RX0_N: length 57.4
  TOP w0.102: v2(57.12,10.58) 57.12,10.58 XP1.29 ; v2(48.18,45.56) 48.18,44.19 45.99,42 40.81,42 40.63,41.82 39.54,41.82 39.36,42 C171.1
  INT_L3 w0.089: v2(57.12,10.58) 56.93,10.4 55.22,10.4 55.05,10.57 55.05,27.95 53.41,29.59 53.41,33.46 55.31,35.37 55.31,42.75 52.05,46.01 48.76,46.01 48.3,45.56 v2(48.18,45.56)
SODIMM_SATA1_RX0_P: length 57.4
  TOP w0.102: v2(48.53,45.33) 48.43,45.23 48.43,44.08 46.09,41.75 40.91,41.75 40.74,41.57 39.69,41.57 39.36,41.24 C173.1 ; v2(57.12,9.97) 57.13,9.98 XP1.27
  INT_L3 w0.089: v2(57.12,9.97) 56.93,10.15 55.12,10.15 54.8,10.47 54.8,27.85 53.17,29.49 53.17,33.56 55.07,35.47 55.07,42.65 51.95,45.77 48.86,45.77 48.53,45.44 v2(48.53,45.33)
SODIMM_SATA1_TX0_N: length 60
  TOP w0.102: v2(46.6,43.47) 46.6,43.42 45.66,42.48 35.1,42.48 C167.1 ; XP1.23 56.96,8.78 v2(56.9,8.73)
  INT_L3 w0.089: v2(46.6,43.47) 46.6,43.2 46.79,43.02 53.15,43.02 54.58,41.59 54.58,36.58 53.93,35.93 53.93,34.97 52.67,33.72 52.67,29.3 54.44,27.53 54.44,22.58 53.94,22.09 53.94,9.82 55.2,8.56 56.74,8.56 v2(56.9,8.73)
SODIMM_SATA1_TX0_P: length 60.8
  TOP w0.102: XP1.21 57,8.18 v2(56.94,8.24) ; C170.1 34.52,42.74 45.56,42.74 46.17,43.35 46.17,43.4 v2(46.19,43.42)
  INT_L3 w0.089: v2(56.94,8.24) 56.86,8.32 55.1,8.32 53.7,9.72 53.7,22.19 54.2,22.68 54.2,27.43 52.43,29.2 52.43,33.82 53.69,35.07 53.69,36.03 54.33,36.68 54.33,41.49 53.05,42.77 46.69,42.77 46.26,43.21 46.26,43.36 v2(46.19,43.42)
SODIMM_SPI1_CS0: length 47.5
  TOP w0.114: v7(23.51,14.64) 23.43,14.73 R258.2
  SIG_L5 w0.091: v7(23.51,14.64) 24.21,14.64 29.84,9.02 34.75,9.02 35.31,9.58 36.63,9.58 37.02,9.2 41.2,9.2 44.63,12.63 45.08,12.63 48.87,16.42 48.87,19.28 49.62,20.03 49.62,22.11 v3(49.98,22.47)
  SIG_L10 w0.091: v5(49.98,22.95) 50,22.92 50,22.52 49.98,22.49 v3(49.98,22.47)
  BOTTOM w0.114: XP1.72 52.27,23.18 52.04,22.95 v5(49.98,22.95)
SODIMM_SPI1_D0: length 49.3
  TOP w0.114: R255.2 22.61,14.36 22.31,14.05 v7(22.31,14.04)
  SIG_L5 w0.091: v7(22.31,14.04) 22.7,14.04 24.95,11.79 25.96,11.79 30.27,7.49 40.42,7.49 44.42,11.49 46.46,11.49 49.84,14.87 49.84,18.02 50.21,18.4 50.21,18.57 50.82,19.17 50.82,20.94 v3(51.05,21.17)
  SIG_L10 w0.091: v3(51.05,21.17) 51.2,21.02 51.4,21.02 51.43,21.05 v5(51.51,21.05)
  BOTTOM w0.114: XP1.66 52.8,21.38 52.77,21.35 51.81,21.35 v5(51.51,21.05)
SODIMM_SPI1_D1: length 57.2
  SIG_L5 w0.091: v3(50.97,21.85) 51.65,21.17 51.65,17.97 50.13,16.45 50.13,14.85 46.35,11.07 44.31,11.07 40.51,7.27 30.18,7.27 25.87,11.57 24.86,11.57 22.96,13.48 v3(22.7,13.48)
  SIG_L10 w0.091: v5(51.36,21.57) 51.08,21.85 50.97,21.85 v3(50.97,21.85) ; v3(22.7,13.48) v5(23.28,13.48)
  BOTTOM w0.114: v5(23.28,13.48) 23.33,13.42 29,13.42 29.3,13.73 29.3,15.08 R254.2 ; v5(51.36,21.57) 51.36,21.59 51.75,21.98 XP1.68
SODIMM_SPI1_SCLK: length 49.8
  TOP w0.114: R253.2 21.81,15.3 21.81,15.05 v7(22.14,14.71)
  SIG_L5 w0.091: v7(22.14,14.71) 22.4,14.71 25.11,12.01 26.06,12.01 29.5,8.56 41.18,8.56 44.33,11.71 46.37,11.71 49.62,14.96 49.62,18.11 49.99,18.49 49.99,18.66 50.48,19.15 50.48,21.02 v3(50.06,21.45)
  SIG_L10 w0.091: v5(50.06,21.93) v3(50.06,21.45)
  BOTTOM w0.114: XP1.70 50.7,22.58 v5(50.06,21.93)
SODIMM_UART1_RXD: length 50.1
  TOP w0.114: v2(21.44,12.73) 21.44,13.16 19.45,15.15 R250.2
  INT_L3 w0.091: v3(21.9,12.58) 21.89,12.58 21.89,12.59 21.56,12.59 21.44,12.7 v2(21.44,12.73)
  SIG_L5 w0.091: v3(52.75,18.15) 50.57,15.97 50.57,14.67 46.53,10.64 44.51,10.64 40.63,6.75 32.47,6.75 32.23,6.51 26.87,6.51 22.99,10.39 22.99,11.49 v3(21.9,12.58)
  SIG_L10 w0.091: v5(53.05,18.53) 53.03,18.51 53.03,18.5 52.75,18.22 v3(52.75,18.15)
  BOTTOM w0.114: XP1.60 54.18,19.58 53.13,18.53 v5(53.05,18.53)
SODIMM_UART1_TXD: length 49
  SIG_L5 w0.091: v3(49.93,19.55) 49.93,18.9 49.78,18.75 49.78,18.58 49.09,17.89 49.09,16.33 45.17,12.41 44.72,12.41 41.09,8.78 29.59,8.78 26.15,12.23 25.24,12.23 21.51,15.96 v3(20.82,15.96)
  SIG_L10 w0.091: v5(21.05,17.41) 20.85,17.21 20.85,15.99 v3(20.82,15.96) ; v3(49.93,19.55) 50.44,19.55 v5(50.66,19.32)
  BOTTOM w0.114: v5(21.05,17.41) 21,17.41 20.9,17.51 R251.2 20.75,17.51 ; v5(50.66,19.32) 53.28,19.32 54.14,20.18 XP1.62
SODIMM_UART2_RXD: length 83.3
  TOP w0.114: R256.2 18.7,15.31 20.97,13.04 20.97,11.98 v7(21.58,11.37) ; v7(55.9,50.61) 56.07,50.78 XP1.155
  SIG_L5 w0.091: v7(21.58,11.37) 21.58,11.18 26.69,6.07 32.41,6.07 32.65,6.31 41.63,6.31 45.52,10.2 45.52,10.2 46.71,10.2 51.4,14.88 51.4,15.74 53.44,17.79 53.44,20.78 51.25,22.97 51.25,30.04 53.07,31.85 53.07,33.16 53.6,33.69 53.6,36.44 55.74,38.58 55.74,47.4 56.04,47.71 56.04,50.46 v7(55.9,50.61)
SODIMM_UART2_TXD: length 81.7
  TOP w0.114: v7(55.64,49.92) 56.13,49.92 56.38,50.18 XP1.153 ; R257.2 20.25,14.91 21.78,13.37 21.78,12.59 v2(21.48,12.28)
  INT_L3 w0.091: v3(21.91,11.98) 21.89,11.98 21.58,12.28 v2(21.48,12.28)
  SIG_L5 w0.091: v3(21.91,11.98) 22.57,11.32 22.57,10.5 26.78,6.29 32.32,6.29 32.56,6.53 41.54,6.53 45.43,10.42 46.62,10.42 51.14,14.94 51.14,15.79 53.23,17.88 53.23,20.69 51.04,22.88 51.04,30.13 52.85,31.95 52.85,33.25 53.38,33.78 53.38,36.53 55.52,38.67 55.52,47.5 55.64,47.62 v7(55.64,49.92)
SODIMM_UART5_RXD: length 78
  TOP w0.114: v7(56.25,64.4) 56.43,64.58 XP1.201 ; v2(27.73,14.13) 27.68,14.13 27.18,14.63 R213.2
  INT_L3 w0.091: v3(27.68,13.65) 27.68,14.03 27.73,14.08 27.73,14.13 v2(27.73,14.13)
  SIG_L5 w0.091: v3(27.68,13.65) 28.39,13.65 29.2,12.84 33.93,12.84 34.57,12.19 36.28,12.19 36.48,12.39 42.74,12.39 48.07,17.72 48.07,19.4 48.91,20.24 48.91,23.59 49.69,24.37 49.69,30.3 50.23,30.84 50.23,32.96 52.24,34.98 52.24,39.9 54.83,42.48 54.83,51.35 55.65,52.16 55.65,53.24 55.33,53.56 55.33,62.51 56.25,63.43 v7(56.25,64.4)
SODIMM_UART5_TXD: length 82.2
  TOP w0.114: XP1.197 v2(58.06,63.38)
  INT_L3 w0.091: v3(34.63,15.37) 33.69,15.37 30.5,12.18 v3(29.91,12.18) ; v3(58.54,63.08) 58.24,63.38 v2(58.06,63.38)
  SIG_L10 w0.091: v3(29.91,12.18) 29.91,12.23 28.97,13.17 v5(28.97,13.88) ; v3(34.63,15.37) 34.64,15.37 34.76,15.25 43.6,15.25 49.06,20.72 49.06,26.17 47.39,27.84 47.39,29.62 46.9,30.11 46.9,32.96 47.62,33.68 47.62,33.86 47.62,37.44 47.16,37.9 47.16,39.59 50.16,42.58 55.66,42.58 55.96,42.28 58.2,42.28 59.21,43.3 59.21,55.6 59.02,55.79 59.02,62.55 58.54,63.03 v3(58.54,63.08)
  BOTTOM w0.114: R215.2 27.56,15.12 28.77,13.91 28.95,13.91 v5(28.97,13.88)
SODIMM_UART7_RXD/GPIO5_13: length 76.4
  TOP w0.114: XP1.199 55.66,63.98 v7(55.57,64.07)
  INT_L3 w0.091: v2(28.03,15.1) 28.03,14.62 v3(27.98,14.57)
  SIG_L5 w0.091: v7(55.57,64.07) 55.57,63.36 55.11,62.9 55.11,53.47 55.43,53.15 55.43,52.28 54.55,51.39 54.55,42.51 52.03,39.99 52.03,35.07 50.01,33.05 50.01,30.93 49.48,30.39 49.48,24.47 48.69,23.68 48.69,20.33 47.85,19.49 47.85,17.81 42.65,12.61 36.39,12.61 36.19,12.41 34.66,12.41 34.02,13.06 29.49,13.06 v3(27.98,14.57)
SODIMM_UART7_TXD/GPIO5_14: length 86.6
  TOP w0.114: XP1.203 v1(58.28,65.18)
  GND_L2 w0.091: v1(58.28,65.18) v2(57.89,65.18)
  INT_L3 w0.091: v2(57.89,65.18) v3(57.89,64.7)
  SIG_L5 w0.091: v3(57.89,64.7) 59.24,63.35 59.24,30.7 55.35,26.81 55.35,22.36 55.95,21.75 55.95,13.24 49.74,7.02 v3(47.9,7.02)
  SIG_L10 w0.091: v3(47.9,7.02) 47.74,7.02 46.55,8.22 38.96,8.22 36.11,11.07 35.44,11.07 35.08,11.07 34.55,11.6 33.72,11.6 31.21,14.11 v5(31.21,14.75)
  BOTTOM w0.114: v5(31.21,14.75) 31.21,14.92 30.96,15.17 R210.2
SODIMM_UART8_RXD: length 43.5
  SIG_L5 w0.091: v3(56,6.54) 55.57,6.97 53.78,6.97 52.73,5.91 46.77,5.91 v3(46.45,6.24)
  SIG_L10 w0.091: v5(58.08,17.79) 57.93,17.64 57.93,10.96 57.89,10.92 57.89,10.57 56,8.67 v3(56,6.54) ; v3(46.45,6.24) 46.07,6.62 45.43,6.62 44.26,7.79 38.02,7.79 37.13,8.67 35.17,8.67 29.94,13.91 29.94,14.57 v5(29.86,14.64)
  BOTTOM w0.114: v5(29.86,14.64) 30.02,14.8 R249.2
SODIMM_UART8_TXD: length 44.4
  SIG_L5 w0.091: v3(45.81,6.16) 45.86,6.16 46.56,5.47 54.19,5.47 v3(55.29,6.57)
  SIG_L10 w0.091: v3(45.81,6.16) 45.42,6.16 44.17,7.4 36.14,7.4 35.97,7.57 35.97,7.57 29.02,14.52 v5(28.97,14.52) ; v3(55.29,6.57) 55.72,7 55.72,8.74 57.68,10.69 57.68,18.02 v5(58.03,18.38)
  BOTTOM w0.114: v5(28.97,14.52) 28.92,14.52 28.9,14.54 28.85,14.54 28.4,14.99 R248.2
SODIMM_UART9_RXD: length 64.3
  TOP w0.114: XP1.157 v2(57.55,51.38)
  TOP w0.12: v8(21.47,20.77) U6.E25
  INT_L3 w0.091: v3(45.66,52.11) 45.71,52.06 56.48,52.06 57.16,51.38 v2(57.55,51.38)
  SIG_L5 w0.091: v8(21.47,20.77) 21.86,20.38 22.37,20.38 22.39,20.4 22.42,20.4 22.64,20.62 22.64,20.89 22.95,21.2 25.01,21.2 25.89,22.08 25.89,22.53 26.11,22.75 26.56,22.75 26.69,22.88 26.69,23.33 26.91,23.55 27.36,23.55 27.49,23.68 27.49,24.13 27.71,24.35 28.59,24.35 28.97,24.72 28.97,24.86 29.29,25.18 29.61,25.18 29.94,25.51 29.94,32.4 29.98,32.45 29.98,42.03 30.01,42.06 30.01,42.23 31.89,44.11 40.81,44.11 41.7,45 41.7,48.15 42.64,49.09 42.64,49.67 45.08,52.11 v3(45.66,52.11)
SODIMM_UART9_TXD: length 68.2
  TOP w0.114: XP1.147 v2(57.57,48.38)
  TOP w0.12: v8(19.88,19.18) U6.C27
  INT_L3 w0.091: v2(57.57,48.38) 57.57,48.53 57.01,49.09 57.01,50.36 55.85,51.52 46.16,51.52 45.78,51.14 v3(45.46,51.14)
  SIG_L5 w0.091: v8(19.88,19.18) 20.32,18.73 22.67,18.73 23.54,19.6 24.91,19.6 25.7,20.38 26.46,20.38 27.48,21.41 27.48,21.77 28.54,22.82 28.81,22.82 28.92,22.93 28.92,23.25 29.27,23.6 30.13,23.6 30.62,24.09 30.62,29.98 30.42,30.18 30.42,41.85 31.94,43.37 40.94,43.37 42.2,44.63 42.2,47.73 45.46,50.99 v3(45.46,51.14)
SODIMM_UART10_RXD: length 61
  TOP w0.114: v2(53.03,39.71) 55.21,39.71 55.92,39 57.04,39 57.26,38.78 XP1.115 ; v7(25.26,14.16) 25.34,14.23 R174.2
  INT_L3 w0.091: v3(52.93,39.26) 52.93,39.26 52.93,39.61 v2(53.03,39.71)
  SIG_L5 w0.091: v7(25.26,14.16) 29.59,9.84 30.53,9.84 31.13,9.24 34.66,9.24 35.22,9.8 36.72,9.8 37.11,9.42 41.11,9.42 44.54,12.85 44.99,12.85 48.65,16.51 48.65,19.37 49.34,20.06 49.34,23.41 50.13,24.19 50.13,30.12 50.66,30.65 50.66,32.78 52.95,35.06 52.95,37.93 53.05,38.03 53.05,39.14 v3(52.93,39.26)
SODIMM_UART10_TXD: length 57.1
  TOP w0.114: v2(52.39,39.33) 55.11,39.33 55.87,38.57 56.96,38.57 57.35,38.18 XP1.113 ; v2(26.26,14.67) 26.37,14.77 R175.2
  INT_L3 w0.091: v2(26.26,14.67) 26.26,14.66 26.26,14.24 v3(26.2,14.19) ; v2(52.39,39.33) 52.42,39.31 52.42,39.03 52.65,38.8 v3(52.65,38.75)
  SIG_L5 w0.091: v3(26.2,14.19) 28.79,11.6 35.99,11.6 36.57,12.17 42.83,12.17 48.43,17.77 48.43,19.46 49.13,20.15 49.13,23.5 49.91,24.28 49.91,30.21 50.45,30.74 50.45,32.87 52.65,35.07 v3(52.65,38.75)
SODIMM_USB1_D_N: length 42.4
  TOP w0.127: v6(32.67,35.97) U6.AC12
  SIG_L10 w0.089: v5(56.79,57.44) 57.04,57.19 57.04,56.69 54.66,54.32 51.21,54.32 49.82,55.72 46.23,55.72 38.97,48.45 38.97,39.89 36.22,37.15 34.06,37.15 33.16,36.25 32.97,36.25 32.7,35.97 v6(32.67,35.97)
  BOTTOM w0.102: v5(56.79,57.44) 56.88,57.35 57.38,57.35 57.41,57.38 XP1.178
SODIMM_USB1_D_P: length 42.4
  TOP w0.127: v6(32.67,36.77) U6.AD12
  SIG_L10 w0.089: v5(56.66,57.06) 56.79,56.93 56.79,56.78 56.6,56.6 56.45,56.6 56.34,56.49 56.34,56.34 56.23,56.22 56.08,56.22 55.96,56.11 55.96,55.96 55.85,55.85 55.7,55.85 55.59,55.73 55.59,55.58 55.47,55.47 55.32,55.47 55.21,55.36 55.21,55.2 55.1,55.09 54.94,55.09 54.83,54.98 54.83,54.83 54.56,54.56 51.31,54.56 49.92,55.96 46.13,55.96 38.73,48.55 38.73,39.99 36.12,37.39 33.96,37.39 33.06,36.49 32.76,36.49 32.67,36.58 v6(32.67,36.77)
  BOTTOM w0.102: XP1.176 57.4,56.78 57.12,57.06 v5(56.66,57.06)
SODIMM_USB1_DRVVBUS: length 33.5
  TOP w0.114: v6(34.25,35.14) 33.88,34.77 U6.AB10
  SIG_L5 w0.091: v6(34.25,35.14) 34.3,35.19 34.89,35.19 35.29,34.79 35.29,33.53 33.89,32.13 33.89,31.82 33.95,31.76 33.95,31.39 33.89,31.33 33.89,31.02 33.95,30.96 33.95,30.11 33.06,29.22 33.06,24.42 33.26,24.22 33.26,23.73 33.06,23.53 33.06,22.16 32.86,21.96 32.47,21.96 32.24,21.72 32.24,21.41 32.02,21.19 31.1,21.19 27.31,17.4 27.31,16.54 26.64,15.87 24.09,15.87 23.53,16.43 21.14,16.43 v3(20.24,17.34)
  SIG_L10 w0.091: v5(19.78,16.93) 20.18,17.34 v3(20.24,17.34)
  BOTTOM w0.114: v5(19.78,16.93) 19.72,16.87 R320.1
SODIMM_USB1_ID: length 85.2
  TOP w0.12: U6.B24 23.05,18.39 23.05,18.13 23.05,17.62 v2(22.98,17.54)
  INT_L3 w0.091: v3(23.31,15.48) 23.31,16.07 22.98,16.4 v2(22.98,17.54)
  SIG_L5 w0.091: v3(34.94,15.87) 34.93,15.87 34.92,15.89 34.76,15.89 34.45,16.2 34.45,17.46 34.64,17.64 34.64,18.73 34.1,19.26 34.1,19.8 33.65,20.25 33.26,20.25 31.74,18.73 29.28,18.73 28.62,18.07 28.3,18.07 27.53,17.31 27.53,16.81 27.53,16.45 26.56,15.48 v3(23.31,15.48)
  SIG_L10 w0.091: v3(34.94,15.87) 34.94,15.82 35.21,15.56 43.58,15.56 48.85,20.83 48.85,26.08 47.55,27.37 47.17,27.75 47.17,29.53 46.68,30.02 46.68,33.05 47.4,33.77 47.4,37.32 46.88,37.83 46.88,39.62 50.07,42.8 55.75,42.8 56.05,42.5 58.11,42.5 59,43.39 59,55.23 v5(58.01,56.22)
SODIMM_USB1_RX0_N: length 39.7
  TOP w0.127: v6(32.67,38.37) U6.AF12
  SIG_L10 w0.089: v5(57.55,59.17) 57.55,59.15 57.39,58.98 57.11,58.98 57,59.09 56.85,59.09 56.73,58.98 56.58,58.98 56.47,59.09 56.31,59.09 56.2,58.98 56.05,58.98 55.93,59.09 55.78,59.09 55.67,58.98 55.51,58.98 55.4,59.09 55.25,59.09 55.13,58.98 46.94,58.98 37.15,49.19 37.15,41.48 36.67,40.99 36.67,39.88 35.92,39.13 33.36,39.13 32.78,38.55 32.78,38.46 32.69,38.37 v6(32.67,38.37)
SODIMM_USB1_RX0_P: length 39.8
  TOP w0.127: v6(32.67,37.57) U6.AE12
  SIG_L10 w0.089: v5(57.57,58.61) 57.43,58.74 47.04,58.74 37.39,49.09 37.39,41.38 36.91,40.89 36.91,39.78 36.02,38.89 33.46,38.89 33.02,38.45 33.02,38.23 32.67,37.88 v6(32.67,37.57)
SODIMM_USB1_TX0_N: length 3.7
  BOTTOM w0.102: C166.2 55.58,60.51 56.3,60.51 56.59,60.81 57.13,60.81 57.31,60.98 XP1.190
SODIMM_USB1_TX0_P: length 3.7
  BOTTOM w0.102: XP1.188 57.31,60.38 57.13,60.55 56.7,60.55 56.4,60.26 55.58,60.26 C165.2
SODIMM_USB2_D_N: length 42.1
  TOP w0.127: v6(33.47,38.37) U6.AF11
  SIG_L10 w0.089: v4(53.41,55.15) 53.85,55.15 54.22,55.52 54.22,56.49 53.51,57.19 46.15,57.19 37.94,48.98 37.94,40.18 35.76,38 34.04,38 33.89,38.15 33.69,38.15 v6(33.47,38.37)
  GND_L11 w0.089: v5(53.41,55.15) v4(53.41,55.15)
  BOTTOM w0.102: XP1.170 57.31,54.98 57.13,55.15 v5(53.41,55.15)
SODIMM_USB2_D_P: length 42
  TOP w0.127: v6(33.47,37.57) U6.AE11
  SIG_L10 w0.089: v5(53.43,55.56) 53.43,55.49 53.53,55.39 53.75,55.39 53.98,55.62 53.98,56.39 53.41,56.95 52.85,56.95 52.73,56.83 52.58,56.83 52.46,56.95 52.31,56.95 52.19,56.83 52.05,56.83 51.93,56.95 51.78,56.95 51.66,56.83 51.51,56.83 51.39,56.95 51.25,56.95 51.13,56.83 50.98,56.83 50.86,56.95 46.25,56.95 38.18,48.88 38.18,40.08 35.86,37.76 33.94,37.76 33.79,37.91 33.56,37.91 33.47,37.82 v6(33.47,37.57)
  BOTTOM w0.102: XP1.172 57.31,55.58 57.13,55.41 53.59,55.41 v5(53.43,55.56)
SODIMM_USB2_DRVVBUS: length 36.9
  TOP w0.114: U6.AC10 v2(34.23,35.93)
  INT_L3 w0.091: v3(40.63,38.49) 39.95,39.18 37.48,39.18 v2(34.23,35.93)
  SIG_L5 w0.091: v3(48.61,51.12) 47.04,49.55 46.11,49.55 45.58,49.02 45.58,46.79 44.32,45.54 44.32,41.73 42.39,39.79 42.39,39.46 41.42,38.49 v3(40.63,38.49)
  SIG_L10 w0.091: v3(48.61,51.12) v5(49.09,51.12)
  BOTTOM w0.114: v5(49.09,51.12) 50.77,49.44 54.09,49.44 55.67,51.02 56.22,51.02 56.46,50.78 XP1.156
SODIMM_USB_VBUS: length 22
  TOP w0.114: R47.2 42.04,57.05 42.38,56.71 v2(42.38,55.77)
  INT_L3 w0.091: v2(42.38,55.77) 42.38,53.84 42.56,53.66 43.4,53.66 43.98,54.24 53.41,54.24 v3(55.95,56.78) 55.95,56.86 55.8,57.01 v2(55.8,57.26)
  SIG_L10 w0.091: v3(55.95,56.78) 55.95,57.47 56.71,58.23 57.45,58.23 v5(57.68,58)
SODIMM_VIN4A_CLK0: length 62.5
  TOP w0.114: XP1.161 56.47,52.58 v2(56.35,52.46)
  INT_L3 w0.091: v3(33.21,18.31) 33.21,18.57 v2(33.04,18.74) ; v3(55.03,52.52) 55.13,52.41 56.3,52.41 v2(56.35,52.46)
  SIG_L5 w0.091: v3(55.03,52.52) 54.07,51.56 54.07,49.99 53.14,49.06 52,49.06 50.75,47.81 50.75,36.1 49.41,34.76 48.52,34.76 47.69,33.93 47.69,20.74 46.91,19.95 46.91,18.1 42.99,14.18 33.97,14.18 32.78,15.38 32.78,17.03 33.21,17.46 v3(33.21,18.31)
SODIMM_VIN4A_D0: length 38.3
  TOP w0.114: v2(37.16,16.94) 37.01,16.94 36.68,17.27 36.68,18.39 36.3,18.77 U6.B7
  TOP w0.12: 36.29,18.76 U6.B7
  INT_L3 w0.091: v3(36.8,17.92) 36.72,17.84 36.72,17.26 37,16.98 37.12,16.98 v2(37.16,16.94)
  SIG_L5 w0.091: v3(36.8,17.92) 36.72,17.84 36.72,17.26 37.35,16.63 42.16,16.63 44.1,18.57 44.1,21.84 44.47,22.21 44.47,24.85 45.39,25.78 45.39,26.54 v3(45.76,26.91)
  SIG_L10 w0.091: v3(45.76,26.91) 45.76,26.73 45.94,26.56 v5(45.94,26.48)
  BOTTOM w0.114: XP1.94 56.92,32.18 55.82,31.08 55.82,29.41 53.68,27.27 51.22,27.27 50.44,26.48 v5(45.94,26.48)
SODIMM_VIN4A_D1: length 36.5
  TOP w0.114: U6.B8 35.49,18.77 35.88,18.38 35.88,17.27 v2(35.85,17.24)
  INT_L3 w0.091: v2(35.85,17.24) 35.73,17.36 v3(35.73,17.69)
  SIG_L5 w0.091: v3(35.73,17.69) 36.03,17.39 36.03,17.25 37.22,16.07 42.21,16.07 44.54,18.39 44.54,21.66 44.95,22.07 44.95,24.47 v3(46.12,25.64)
  SIG_L10 w0.091: v3(46.12,25.64) v5(46.58,25.64)
  BOTTOM w0.114: v5(46.58,25.64) 46.7,25.64 46.73,25.67 50.13,25.67 51.43,26.96 51.77,26.96 53.72,26.96 56.06,29.31 56.06,30.84 56.81,31.58 XP1.92
SODIMM_VIN4A_D2: length 50.9
  TOP w0.12: U6.A7 36.27,17.08 36.8,16.55 37.89,16.55 v2(37.91,16.57)
  INT_L3 w0.091: v2(37.91,16.57) 37.91,16.88 37.89,16.9 v3(37.89,17.03)
  SIG_L5 w0.091: v3(37.89,17.03) 41.61,17.03 43.88,19.3 43.88,24.69 45.18,25.99 45.18,27.89 46.06,28.77 46.06,45.22 48.22,47.38 v3(48.43,47.38)
  SIG_L10 w0.091: v3(48.43,47.38) 48.53,47.49 v5(49.37,47.49)
  BOTTOM w0.114: v5(49.37,47.49) 53.79,47.49 54.69,46.58 XP1.142
SODIMM_VIN4A_D3: length 53.9
  TOP w0.114: U6.A8 35.47,17.13 35.83,16.78 36.06,16.78 36.09,16.75 v2(36.14,16.75)
  INT_L3 w0.091: v3(36.33,16.33) 36.33,16.42 36.15,16.6 36.15,16.69 36.14,16.7 v2(36.14,16.75)
  SIG_L5 w0.091: v3(36.33,16.33) 36.88,15.77 42.23,15.77 44.76,18.3 44.76,21.57 45.23,22.04 45.23,23.93 46.57,25.27 46.57,32.13 46.57,33.7 46.57,34.43 46.57,34.43 46.57,44.26 48.86,46.55 v3(48.86,48.35)
  SIG_L10 w0.091: v3(48.86,48.35) 49.22,48.35 v5(49.72,47.84)
  BOTTOM w0.114: XP1.144 54.78,47.18 54.12,47.84 v5(49.72,47.84)
SODIMM_VIN4A_D4: length 57.8
  TOP w0.12: v8(35.07,19.17) U6.C9
  SIG_L10 w0.091: v8(35.07,19.17) 35.07,18.92 35.47,18.52 35.47,18.19 35.24,17.95 35.24,17.5 35.91,16.83 36.54,16.83 37.51,15.86 43.5,15.86 48.41,20.77 48.41,26.2 47.46,27.15 46.73,27.88 46.73,29.66 46.46,29.93 46.46,33.14 46.64,33.32 47.15,33.83 47.15,35.76 47.15,36.92 46.52,37.55 46.52,39.88 49.79,43.14 55.72,43.14 56.14,42.72 58.02,42.72 58.67,43.37 58.67,47.43 v5(58.31,47.79)
  BOTTOM w0.114: 58.18,47.8 58.49,47.8 58.51,47.78 XP1.146
SODIMM_VIN4A_D5: length 54.9
  TOP w0.114: v2(34.74,17.03) 34.67,17.1
  TOP w0.12: 34.67,17.1 U6.A9
  INT_L3 w0.091: v3(34.86,16.53) 34.74,16.65 v2(34.74,17.03)
  SIG_L5 w0.091: v3(34.86,16.53) 36.34,15.05 42.44,15.05 46.03,18.64 46.03,20.31 46.21,20.49 46.21,23.98 47.03,24.8 47.03,42.48 50.16,45.61 v3(50.16,48.53)
  SIG_L10 w0.091: v3(50.16,48.53) 50.3,48.38 v5(51.1,48.38)
  BOTTOM w0.114: XP1.148 v5(51.1,48.38)
SODIMM_VIN4A_D6: length 34.2
  TOP w0.114: U6.B9 34.7,18.77 35.08,18.39 35.08,17.12 v2(35.12,17.08)
  INT_L3 w0.091: v2(35.12,17.08) 35.12,17 35.41,16.71 35.41,16.63 v3(35.44,16.6)
  SIG_L5 w0.091: v3(35.44,16.6) 35.44,16.34 36.5,15.27 42.35,15.27 45.81,18.73 45.81,20.41 45.85,20.44 45.85,20.96 v3(45.59,21.22)
  SIG_L10 w0.091: v5(45.05,22.24) 45.56,21.73 45.56,21.25 v3(45.59,21.22)
  BOTTOM w0.114: XP1.74 57.26,26.18 57.12,26.32 55.94,26.32 54.37,24.75 52.87,24.75 51.63,23.51 49.09,23.51 47.87,22.29 45.1,22.29 v5(45.05,22.24)
